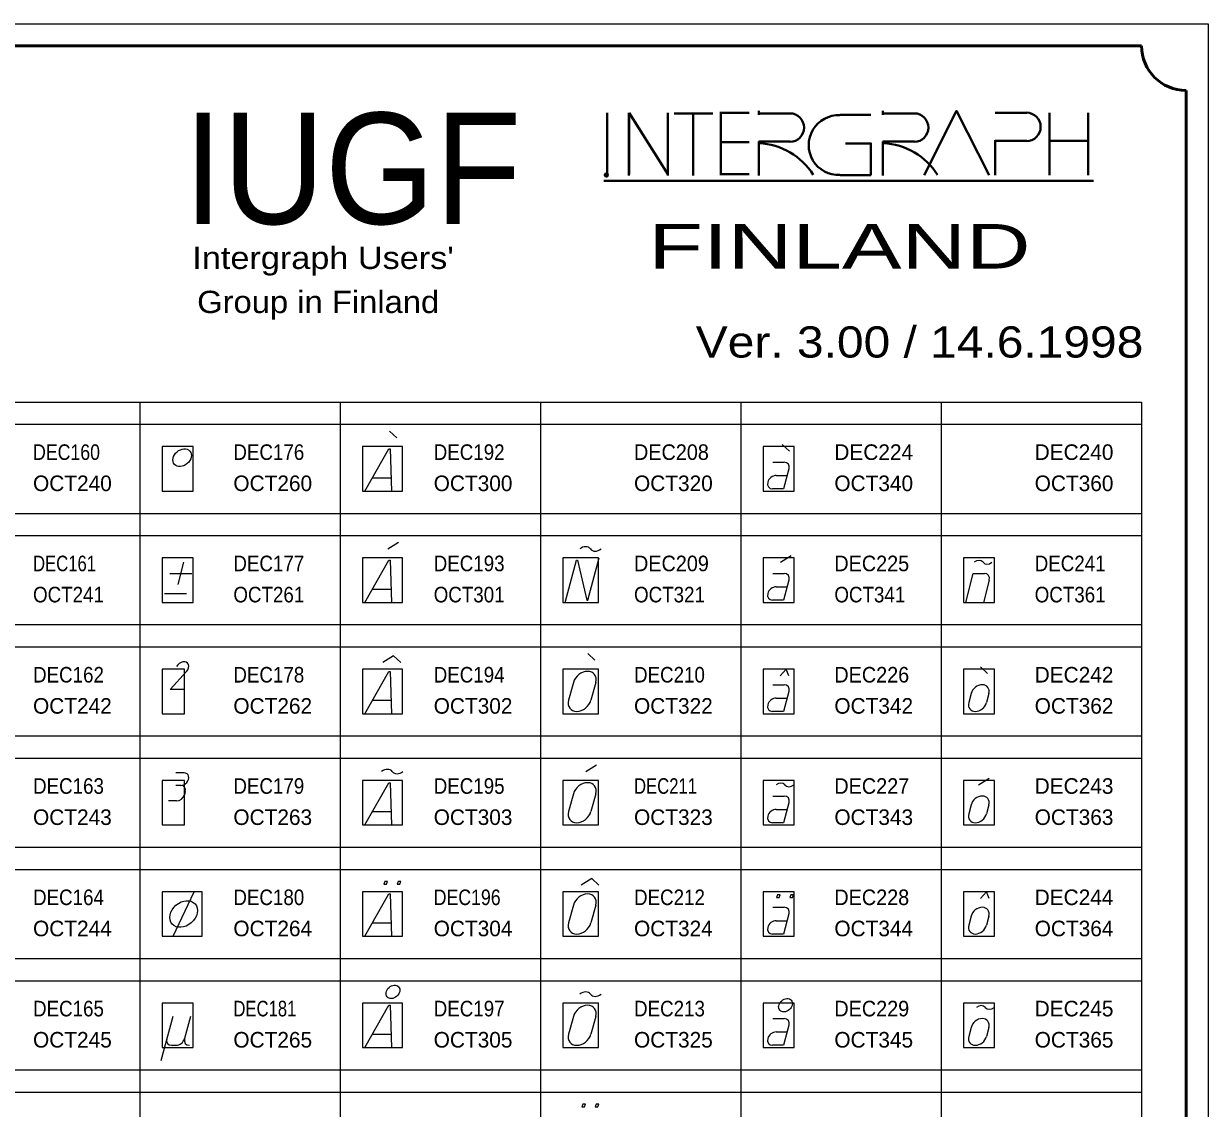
# Model space of a CAD drawing. Extents: x -200 to 7300, y -200 to 4800.
# Drawn here: x 4639 to 7300, y 2364 to 4800 of the extents above; entities that cross this region are included whole.
import ezdxf
from ezdxf.enums import TextEntityAlignment as Align

# ---------------------------------------------------------------- set-up
doc = ezdxf.new("R2010")
doc.units = 0
doc.header["$LTSCALE"] = 14
doc.header["$PDMODE"] = 32
doc.header["$PDSIZE"] = 7
for name, color, linetype, lineweight in [('1', 7, 'Continuous', 13), ('5', 7, 'Continuous', 40), ('6', 7, 'Continuous', 13), ('63', 7, 'Continuous', 13)]:
    doc.layers.add(name, color=color, linetype=linetype, lineweight=lineweight)
doc.layers.add('10', color=7, linetype='Continuous')
doc.layers.add('11', color=7, linetype='Continuous')

msp = doc.modelspace()

# ---------------------------------------------------------------- linework, layer by layer
at = {"layer": '1'}
for p, q in [((5477, 3870), (5461, 3885)), ((6359, 3840), (6343, 3855)), ((6322, 3815), (6347, 3815)), ((5422, 3780), (5464, 3780)), ((6329, 3785), (6354, 3785)), ((5457, 3620), (5481, 3635)), ((6339, 3590), (6363, 3605)), ((4986, 3540), (4999, 3590)), ((4967, 3565), (5017, 3565)), ((6322, 3565), (6347, 3565)), ((6808, 3550), (6795, 3500)), ((4955, 3520), (5005, 3520)), ((5422, 3530), (5464, 3530)), ((6329, 3535), (6354, 3535)), ((5922, 3370), (5906, 3385)), ((6804, 3340), (6788, 3355)), ((5874, 3320), (5863, 3280)), ((5924, 3320), (5913, 3280)), ((6322, 3315), (6347, 3315)), ((5422, 3280), (5464, 3280)), ((6329, 3285), (6354, 3285)), ((6767, 3295), (6762, 3275)), ((6807, 3295), (6802, 3275)), ((4999, 3117), (4981, 3117)), ((5902, 3120), (5926, 3135)), ((4992, 3089), (4981, 3089)), ((6784, 3090), (6808, 3105)), ((5002, 3075), (5000, 3068)), ((5874, 3070), (5863, 3030)), ((5924, 3070), (5913, 3030)), ((6322, 3065), (6347, 3065)), ((4982, 3054), (4964, 3054)), ((6329, 3035), (6354, 3035)), ((6767, 3045), (6762, 3025)), ((6807, 3045), (6802, 3025)), ((5422, 3030), (5464, 3030)), ((4975, 2750), (5022, 2850)), ((5874, 2820), (5863, 2780)), ((5924, 2820), (5913, 2780)), ((6322, 2815), (6347, 2815)), ((6767, 2795), (6762, 2775)), ((6807, 2795), (6802, 2775)), ((5422, 2780), (5464, 2780)), ((6329, 2785), (6354, 2785)), ((4974, 2570), (4947, 2470)), ((5014, 2570), (5000, 2520)), ((5874, 2570), (5863, 2530)), ((5924, 2570), (5913, 2530)), ((6322, 2565), (6347, 2565)), ((5422, 2530), (5464, 2530)), ((6329, 2535), (6354, 2535)), ((6767, 2545), (6762, 2525)), ((6807, 2545), (6802, 2525)), ((4971, 2505), (4981, 2505))]:
    msp.add_line(p, q, dxfattribs=at)
for points in [[(5405, 3750), (5459, 3845), (5462, 3845), (5465, 3750)], [(6358, 3800), (6346, 3755), (6321, 3755)], [(5405, 3500), (5459, 3595), (5462, 3595), (5465, 3500)], [(5855, 3500), (5881, 3595), (5883, 3595), (5904, 3505), (5906, 3505), (5932, 3600)], [(6358, 3550), (6346, 3505), (6321, 3505)], [(6755, 3500), (6772, 3565), (6797, 3565)], [(5486, 3365), (5470, 3380), (5446, 3365)], [(4999, 3304), (4968, 3304), (5005, 3345)], [(5405, 3250), (5459, 3345), (5462, 3345), (5465, 3250)], [(6358, 3335), (6352, 3350), (6338, 3335)], [(6358, 3300), (6346, 3255), (6321, 3255)], [(5405, 3000), (5459, 3095), (5462, 3095), (5465, 3000)], [(6358, 3050), (6346, 3005), (6321, 3005)], [(5931, 2865), (5915, 2880), (5891, 2865)], [(6808, 2835), (6802, 2850), (6788, 2835)], [(5405, 2750), (5459, 2845), (5462, 2845), (5465, 2750)], [(6358, 2800), (6346, 2755), (6321, 2755)], [(5405, 2500), (5459, 2595), (5462, 2595), (5465, 2500)], [(6358, 2550), (6346, 2505), (6321, 2505)]]:
    msp.add_lwpolyline(points, dxfattribs=at)
for points in [[(5448, 2867), (5454, 2867), (5456, 2873), (5450, 2873)], [(5478, 2867), (5484, 2867), (5486, 2873), (5480, 2873)], [(6330, 2837), (6336, 2837), (6338, 2843), (6332, 2843)], [(6360, 2837), (6366, 2837), (6368, 2843), (6362, 2843)], [(5893, 2367), (5899, 2367), (5901, 2373), (5895, 2373)], [(5923, 2367), (5929, 2367), (5931, 2373), (5925, 2373)]]:
    msp.add_lwpolyline(points, close=True, dxfattribs=at)
for centre, major_axis in [((4994.91, 3825), (-17.2, -15.05)), ((4998.27, 2800), (-25.8, -22.58)), ((5468.39, 2625), (-12.9, -11.29)), ((6350.36, 2595), (-12.9, -11.29))]:
    msp.add_ellipse(centre, major_axis=major_axis, ratio=0.765566, dxfattribs=at)
for centre, major_axis, start_param, end_param in [((6343.23, 3800), (-12.9, -11.29), 2.2896327, 3.860429), ((6325.19, 3770), (-12.9, -11.29), 3.860429, 7.0020216), ((5896.78, 3608), (-14.6, -12.77), 3.0750308, 4.6457939), ((5927.21, 3632), (-14.6, -12.77), 6.2166235, 7.7873867), ((6781.29, 3580), (-12.16, -10.64), 3.0750308, 4.6458271), ((6806.65, 3600), (-12.16, -10.64), 6.2166235, 7.7874198), ((6343.24, 3550), (-12.9, -11.29), 2.2896327, 3.860429), ((6793, 3550), (-12.9, -11.29), 2.2896327, 3.860429), ((6325.21, 3520), (-12.9, -11.29), 3.860429, 7.0020216), ((4995.28, 3352.61), (-12.04, -10.54), 1.7153279, 5.1862467), ((5899, 3320), (-21.5, -18.81), 2.2896326, 5.4312252), ((6343.26, 3300), (-12.9, -11.29), 2.2896327, 3.860429), ((6787, 3295), (-17.2, -15.05), 2.2896326, 5.4312252), ((5888, 3280), (21.5, 18.81), 2.2896328, 5.4312254), ((6325.22, 3270), (-12.9, -11.29), 3.860429, 7.0020216), ((6782, 3275), (17.2, 15.05), 2.2896328, 5.4312254), ((4995.47, 3102.98), (-12.06, -10.55), 0.646299, 3.8615683), ((5451.8, 3108), (-14.6, -12.77), 3.0750308, 4.6457939), ((5482.23, 3132), (-14.6, -12.77), 6.2166235, 7.7873867), ((4987.96, 3075), (-12.04, -10.54), 2.2896326, 3.8604289), ((5899, 3070), (-21.5, -18.81), 2.2896326, 5.4312252), ((6336.31, 3080), (-12.16, -10.64), 3.0750308, 4.6458271), ((6361.67, 3100), (-12.16, -10.64), 6.2166235, 7.7874198), ((4986.08, 3068), (12.04, 10.54), 3.860429, 5.4312252), ((6343.28, 3050), (-12.9, -11.29), 2.2896327, 3.860429), ((6787, 3045), (-17.2, -15.05), 2.2896326, 5.4312252), ((6325.24, 3020), (-12.9, -11.29), 3.860429, 7.0020216), ((5888, 3030), (21.5, 18.81), 2.2896328, 5.4312254), ((6782, 3025), (17.2, 15.05), 2.2896328, 5.4312254), ((5899, 2820), (-21.5, -18.81), 2.2896326, 5.4312252), ((6343.29, 2800), (-12.9, -11.29), 2.2896327, 3.860429), ((6787, 2795), (-17.2, -15.05), 2.2896326, 5.4312252), ((5888, 2780), (21.5, 18.81), 2.2896328, 5.4312254), ((6325.25, 2770), (-12.9, -11.29), 3.860429, 7.0020216), ((6782, 2775), (17.2, 15.05), 2.2896328, 5.4312254), ((5896.84, 2608), (-14.6, -12.77), 3.0750308, 4.6457939), ((5927.27, 2632), (-14.6, -12.77), 6.2166235, 7.7873867), ((5899, 2570), (-21.5, -18.81), 2.2896326, 5.4312252), ((6786.35, 2580), (-12.16, -10.64), 3.0750308, 4.6458271), ((6811.71, 2600), (-12.16, -10.64), 6.2166235, 7.7874198), ((6343.31, 2550), (-12.9, -11.29), 2.2896327, 3.860429), ((6787, 2545), (-17.2, -15.05), 2.2896326, 5.4312252), ((5888, 2530), (21.5, 18.81), 2.2896328, 5.4312254), ((6325.27, 2520), (-12.9, -11.29), 3.860429, 7.0020216), ((4975.25, 2520), (12.9, 11.29), 2.2896327, 3.860429), ((4985.25, 2520), (-12.9, -11.29), 0.7188363, 2.2896326), ((5015.25, 2520), (12.9, 11.29), 2.2896328, 3.860429), ((6782, 2525), (17.2, 15.05), 2.2896328, 5.4312254)]:
    msp.add_ellipse(centre, major_axis=major_axis, ratio=0.765566, start_param=start_param, end_param=end_param, dxfattribs=at)
at = {"layer": '5', "lineweight": 53}
for p, q in [((-50, 4750), (7150, 4750)), ((7250, 4650), (7250, -50))]:
    msp.add_line(p, q, dxfattribs=at)
at = {"layer": '5'}
for p, q in [((6290, 4595), (6290, 4604)), ((6569, 4595), (6569, 4604)), ((5950, 4459), (5950, 4600)), ((5998, 4459), (5998, 4600)), ((5999, 4462), (5999, 4600)), ((6086, 4462), (5999, 4600)), ((6086, 4459), (6086, 4600)), ((6100, 4598), (6187, 4598)), ((6143, 4459), (6143, 4600)), ((6203, 4600), (6269, 4600)), ((6205, 4600), (6205, 4460)), ((6361, 4598), (6290, 4598)), ((6542, 4595), (6473, 4595)), ((6640, 4598), (6569, 4598)), ((6892, 4600), (6821, 4600)), ((6943, 4460), (6943, 4600)), ((7030, 4460), (7030, 4600)), ((6203, 4534), (6269, 4534)), ((6361, 4535), (6290, 4535)), ((6290, 4459), (6290, 4535)), ((6640, 4535), (6569, 4535)), ((6569, 4459), (6569, 4535)), ((6821, 4460), (6821, 4538)), ((6892, 4537), (6821, 4537)), ((6944, 4537), (7027, 4537)), ((5942, 4447), (7042, 4447)), ((6203, 4462), (6269, 4462)), ((6542, 4460), (6473, 4460))]:
    msp.add_line(p, q, dxfattribs=at)
at = {"layer": '5', "lineweight": 25}
msp.add_lwpolyline([(-200, -200), (-200, 4800), (7300, 4800), (7300, -200)], close=True, dxfattribs=at)
at = {"layer": '5'}
for points in [[(6662, 4460), (6734, 4604), (6808, 4460)], [(6662, 4460), (6734, 4604), (6808, 4460)], [(6542, 4460), (6542, 4531), (6485, 4531)]]:
    msp.add_lwpolyline(points, dxfattribs=at)
at = {"layer": '5', "lineweight": 53}
msp.add_arc((7250.23, 4750.23), 100.23, 180.13245, 269.86755, dxfattribs=at)
at = {"layer": '5'}
for centre, radius, start, end in [((6359.95, 4566.47), 32.08, 270, 89.99999), ((6469.54, 4527.31), 67.13, 87.55561, 272.44438), ((6639.2, 4566.47), 32.08, 270, 89.99999), ((6891.34, 4568.25), 32.08, 270, 89.99999), ((6282.86, 4378.09), 153.83, 32.38854, 87.01955), ((6562.1, 4378.09), 153.83, 32.38854, 87.01955)]:
    msp.add_arc(centre, radius, start, end, dxfattribs=at)
msp.add_point((5948, 4460), dxfattribs=at)
at = {"layer": '6'}
for p, q in [((-50, 3950), (7150, 3950)), ((4900, 3950), (4900, -50)), ((5350, 3950), (5350, -50)), ((5800, 3950), (5800, -50)), ((6250, 3950), (6250, -50)), ((6700, 3950), (6700, -50)), ((7150, 3950), (7150, -50)), ((-50, 3900), (7150, 3900)), ((-50, 3700), (7150, 3700)), ((-50, 3650), (7150, 3650)), ((-50, 3450), (7150, 3450)), ((-50, 3400), (7150, 3400)), ((-50, 3200), (7150, 3200)), ((-50, 3150), (7150, 3150)), ((-50, 2950), (7150, 2950)), ((-50, 2900), (7150, 2900)), ((-50, 2700), (7150, 2700)), ((-50, 2650), (7150, 2650)), ((-50, 2450), (7150, 2450)), ((-50, 2400), (7150, 2400))]:
    msp.add_line(p, q, dxfattribs=at)
at = {"layer": '63'}
for points in [[(4950, 3750), (5020, 3750), (5020, 3850), (4950, 3850)], [(5400, 3750), (5490, 3750), (5490, 3850), (5400, 3850)], [(6300, 3750), (6370, 3750), (6370, 3850), (6300, 3850)], [(4950, 3500), (5020, 3500), (5020, 3600), (4950, 3600)], [(5400, 3500), (5490, 3500), (5490, 3600), (5400, 3600)], [(5850, 3500), (5930, 3500), (5930, 3600), (5850, 3600)], [(6300, 3500), (6370, 3500), (6370, 3600), (6300, 3600)], [(6750, 3500), (6820, 3500), (6820, 3600), (6750, 3600)], [(4950, 3250), (5000, 3250), (5000, 3350), (4950, 3350)], [(5400, 3250), (5490, 3250), (5490, 3350), (5400, 3350)], [(5850, 3250), (5930, 3250), (5930, 3350), (5850, 3350)], [(6300, 3250), (6370, 3250), (6370, 3350), (6300, 3350)], [(6750, 3250), (6820, 3250), (6820, 3350), (6750, 3350)], [(4950, 3000), (5000, 3000), (5000, 3100), (4950, 3100)], [(5400, 3000), (5490, 3000), (5490, 3100), (5400, 3100)], [(5850, 3000), (5930, 3000), (5930, 3100), (5850, 3100)], [(6300, 3000), (6370, 3000), (6370, 3100), (6300, 3100)], [(6750, 3000), (6820, 3000), (6820, 3100), (6750, 3100)], [(4950, 2750), (5040, 2750), (5040, 2850), (4950, 2850)], [(5400, 2750), (5490, 2750), (5490, 2850), (5400, 2850)], [(5850, 2750), (5930, 2750), (5930, 2850), (5850, 2850)], [(6300, 2750), (6370, 2750), (6370, 2850), (6300, 2850)], [(6750, 2750), (6820, 2750), (6820, 2850), (6750, 2850)], [(4950, 2500), (5020, 2500), (5020, 2600), (4950, 2600)], [(5400, 2500), (5490, 2500), (5490, 2600), (5400, 2600)], [(5850, 2500), (5930, 2500), (5930, 2600), (5850, 2600)], [(6300, 2500), (6370, 2500), (6370, 2600), (6300, 2600)], [(6750, 2500), (6820, 2500), (6820, 2600), (6750, 2600)]]:
    msp.add_lwpolyline(points, close=True, dxfattribs=at)

# ---------------------------------------------------------------- texts
at = {"layer": '10'}
for s, width, p in [('DEC160', 0.85, (4660, 3820)), ('DEC176', 0.9, (5110, 3820)), ('DEC192', 0.9, (5560, 3820)), ('DEC208', 0.95, (6010, 3820)), ('DEC161', 0.8, (4660, 3570)), ('DEC177', 0.9, (5110, 3570)), ('DEC193', 0.9, (5560, 3570)), ('DEC209', 0.95, (6010, 3570)), ('DEC225', 0.95, (6460, 3570)), ('DEC241', 0.9, (6910, 3570)), ('DEC162', 0.9, (4660, 3320)), ('DEC178', 0.9, (5110, 3320)), ('DEC194', 0.9, (5560, 3320)), ('DEC210', 0.9, (6010, 3320)), ('DEC226', 0.95, (6460, 3320)), ('DEC163', 0.9, (4660, 3070)), ('DEC179', 0.9, (5110, 3070)), ('DEC195', 0.9, (5560, 3070)), ('DEC211', 0.8, (6010, 3070)), ('DEC227', 0.95, (6460, 3070)), ('DEC164', 0.9, (4660, 2820)), ('DEC180', 0.9, (5110, 2820)), ('DEC196', 0.85, (5560, 2820)), ('DEC212', 0.9, (6010, 2820)), ('DEC228', 0.95, (6460, 2820)), ('DEC165', 0.9, (4660, 2570)), ('DEC181', 0.8, (5110, 2570)), ('DEC197', 0.9, (5560, 2570)), ('DEC213', 0.9, (6010, 2570)), ('DEC229', 0.95, (6460, 2570))]:
    msp.add_text(s, height=35, dxfattribs=dict(at, width=width)).set_placement(p)
for s, p in [('DEC224', (6460, 3820)), ('DEC240', (6910, 3820)), ('DEC242', (6910, 3320)), ('DEC243', (6910, 3070)), ('DEC244', (6910, 2820)), ('DEC245', (6910, 2570))]:
    msp.add_text(s, height=35, dxfattribs=at).set_placement(p)
at = {"layer": '11'}
for s, p in [('OCT240', (4660, 3750)), ('OCT260', (5110, 3750)), ('OCT300', (5560, 3750)), ('OCT320', (6010, 3750)), ('OCT340', (6460, 3750)), ('OCT360', (6910, 3750)), ('OCT242', (4660, 3250)), ('OCT262', (5110, 3250)), ('OCT302', (5560, 3250)), ('OCT322', (6010, 3250)), ('OCT342', (6460, 3250)), ('OCT362', (6910, 3250)), ('OCT243', (4660, 3000)), ('OCT263', (5110, 3000)), ('OCT303', (5560, 3000)), ('OCT323', (6010, 3000)), ('OCT343', (6460, 3000)), ('OCT363', (6910, 3000)), ('OCT244', (4660, 2750)), ('OCT264', (5110, 2750)), ('OCT304', (5560, 2750)), ('OCT324', (6010, 2750)), ('OCT344', (6460, 2750)), ('OCT364', (6910, 2750)), ('OCT245', (4660, 2500)), ('OCT265', (5110, 2500)), ('OCT305', (5560, 2500)), ('OCT325', (6010, 2500)), ('OCT345', (6460, 2500)), ('OCT365', (6910, 2500))]:
    msp.add_text(s, height=35, dxfattribs=at).set_placement(p)
at = {"layer": '11', "width": 0.9}
for s, p in [('OCT241', (4660, 3500)), ('OCT261', (5110, 3500)), ('OCT301', (5560, 3500)), ('OCT321', (6010, 3500)), ('OCT341', (6460, 3500)), ('OCT361', (6910, 3500))]:
    msp.add_text(s, height=35, dxfattribs=at).set_placement(p)
at = {"layer": '5'}
for s, height, width, p in [('IUGF', 250, 0.95, (5377.5, 4350)), ('FINLAND', 100, 1.5, (6471.5, 4250)), ("Intergraph Users'", 50, 1.15, (5311.5, 4249)), ('Group in Finland', 50, 1.1, (5300.5, 4150))]:
    msp.add_text(s, height=height, dxfattribs=dict(at, width=width)).set_placement(p, align=Align.CENTER)
at = {"layer": '5', "width": 1.15}
msp.add_text('Ver. 3.00 / 14.6.1998', height=70, dxfattribs=at).set_placement((7154.1, 4050), align=Align.RIGHT)

doc.saveas('drawing.dxf')
